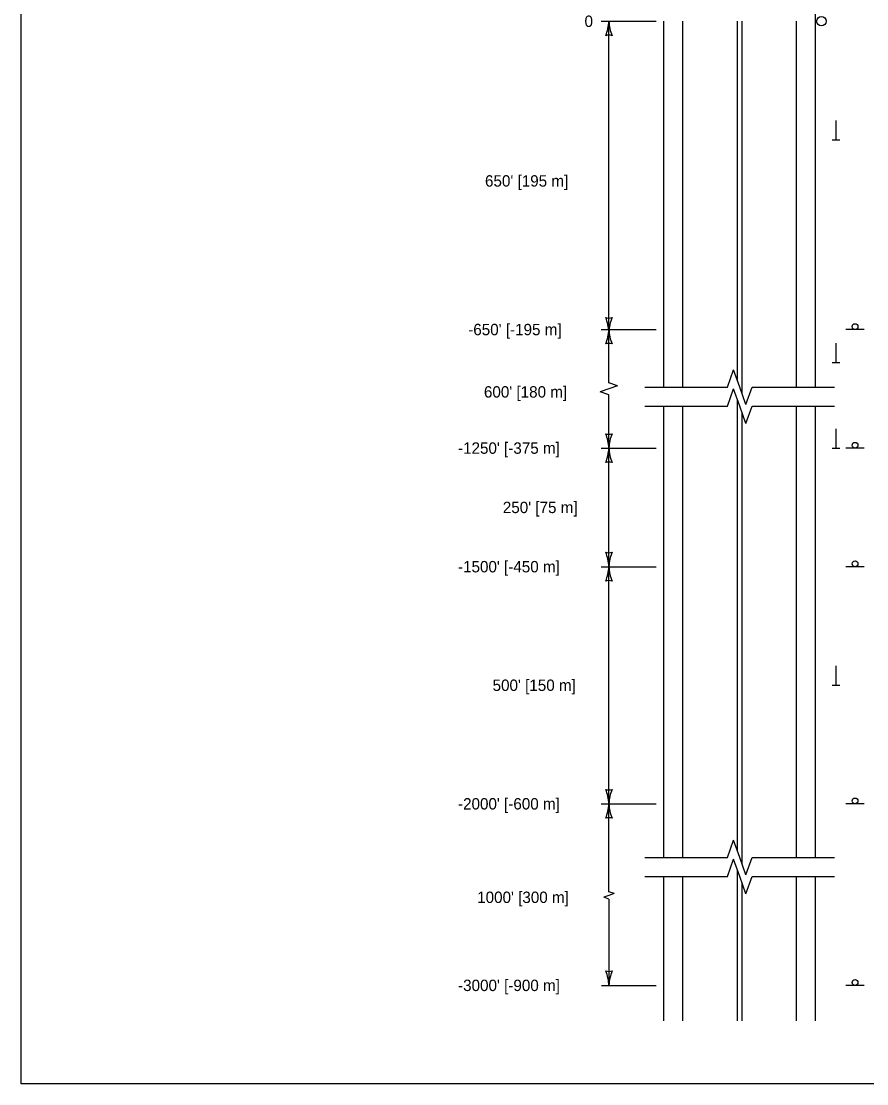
# Model space of a CAD drawing. Extents: x 49991.4 to 50021, y 49987.6 to 50011.4.
# Drawn here: x 49999.38 to 50003.84, y 49987.8 to 49993.4 of the extents above; entities that cross this region are included whole.
import ezdxf

# ---------------------------------------------------------------- set-up
doc = ezdxf.new("R2010")
doc.units = 0
for name, color, linetype in [('Level 1', 7, 'Continuous'), ('Level 2', 7, 'Continuous'), ('Level 3', 7, 'Continuous'), ('Level 6', 7, 'Continuous')]:
    doc.layers.add(name, color=color, linetype=linetype)

msp = doc.modelspace()

# ---------------------------------------------------------------- linework, layer by layer
at = {"layer": 'Level 1'}
for p, q in [((50003.5727, 49991.4704), (50003.5727, 49997.459)), ((50002.7727, 49991.4704), (50002.7727, 49993.3994)), ((50002.8727, 49991.4704), (50002.8727, 49993.3994)), ((50003.1602, 49991.5057), (50003.1602, 49993.3994)), ((50003.1852, 49991.4352), (50003.1852, 49993.3994)), ((50003.4727, 49991.4704), (50003.4727, 49993.3994)), ((50003.6807, 49992.7744), (50003.6807, 49992.8764)), ((50003.6604, 49992.7744), (50003.701, 49992.7744)), ((50003.8287, 49991.7744), (50003.7327, 49991.7744)), ((50003.6807, 49991.5999), (50003.6807, 49991.7018)), ((50003.6604, 49991.5999), (50003.701, 49991.5999)), ((50003.1602, 49989.0262), (50003.1602, 49991.4057)), ((50002.7727, 49988.9909), (50002.7727, 49991.3704)), ((50002.8727, 49988.9909), (50002.8727, 49991.3704)), ((50003.4727, 49988.9909), (50003.4727, 49991.3704)), ((50003.5727, 49988.9909), (50003.5727, 49991.3704)), ((50003.1852, 49988.9556), (50003.1852, 49991.3352)), ((50003.6807, 49991.1494), (50003.6807, 49991.2514)), ((50003.6604, 49991.1494), (50003.701, 49991.1494)), ((50003.8287, 49991.1494), (50003.7327, 49991.1494)), ((50003.8287, 49990.5244), (50003.7327, 49990.5244)), ((50003.6807, 49989.8995), (50003.6807, 49990.0015)), ((50003.6604, 49989.8995), (50003.701, 49989.8995)), ((50003.8287, 49989.2744), (50003.7327, 49989.2744)), ((50002.7727, 49988.1302), (50002.7727, 49988.8909)), ((50002.8727, 49988.1302), (50002.8727, 49988.8909)), ((50003.1602, 49988.1302), (50003.1602, 49988.9262)), ((50003.4727, 49988.1302), (50003.4727, 49988.8909)), ((50003.5727, 49988.1302), (50003.5727, 49988.8909)), ((50003.1852, 49988.1302), (50003.1852, 49988.8556)), ((50003.8287, 49988.3174), (50003.7327, 49988.3174))]:
    msp.add_line(p, q, dxfattribs=at)
msp.add_lwpolyline([(49999.3835, 49998.9992), (50016.7501, 49998.9992), (50016.7501, 49987.7988), (49999.3835, 49987.7988)], close=True, dxfattribs=at)
for centre, radius in [((50003.6032, 49993.3994), 0.025), ((50003.7807, 49991.7896), 0.0152), ((50003.7807, 49991.1646), 0.0152), ((50003.7807, 49990.5396), 0.0152), ((50003.7807, 49989.2896), 0.0152), ((50003.7807, 49988.3326), 0.0152)]:
    msp.add_circle(centre, radius, dxfattribs=at)
at = {"layer": 'Level 3'}
for p, q in [((50002.4427, 49993.3994), (50002.7327, 49993.3994)), ((50002.4827, 49991.7744), (50002.4827, 49993.3994)), ((50002.4427, 49991.7744), (50002.7327, 49991.7744)), ((50002.4827, 49991.4943), (50002.4827, 49991.7744)), ((50002.4827, 49991.4619), (50002.437, 49991.4457)), ((50002.5284, 49991.4781), (50002.4827, 49991.4943)), ((50002.5284, 49991.4781), (50002.4827, 49991.4619)), ((50002.4827, 49991.4295), (50002.437, 49991.4457)), ((50002.4827, 49991.1494), (50002.4827, 49991.4295)), ((50002.4427, 49991.1494), (50002.7327, 49991.1494)), ((50002.4827, 49990.5244), (50002.4827, 49991.1494)), ((50002.4827, 49990.5244), (50002.4827, 49990.7003)), ((50002.4427, 49990.5244), (50002.7327, 49990.5244)), ((50002.4827, 49989.2744), (50002.4827, 49990.5244)), ((50002.4427, 49989.2744), (50002.7327, 49989.2744)), ((50002.4827, 49988.8107), (50002.4827, 49989.2744)), ((50002.4826, 49988.7913), (50002.4552, 49988.7816)), ((50002.4827, 49988.7719), (50002.4552, 49988.7816)), ((50002.51, 49988.801), (50002.4826, 49988.7913)), ((50002.51, 49988.801), (50002.4827, 49988.8107)), ((50002.4827, 49988.7719), (50002.483, 49988.3174)), ((50002.443, 49988.3174), (50002.7327, 49988.3174))]:
    msp.add_line(p, q, dxfattribs=at)
for centre, radius, start, end in [((50002.2606, 49993.4086), 0.2223, 337.456, 357.6395), ((50002.7154, 49993.4109), 0.233, 182.8273, 202.0772), ((50002.4827, 49993.2712), 0.0548, 72.1388, 107.8612), ((50002.4827, 49991.8895), 0.0548, 252.1388, 287.8612), ((50002.25, 49991.7498), 0.233, 2.8273, 22.0772), ((50002.7048, 49991.7521), 0.2223, 157.456, 177.6395), ((50002.2606, 49991.7836), 0.2223, 337.456, 357.6395), ((50002.7154, 49991.7859), 0.233, 182.8273, 202.0772), ((50002.4827, 49991.6462), 0.0548, 72.1388, 107.8612), ((50002.4827, 49991.2776), 0.0548, 252.1388, 287.8612), ((50002.25, 49991.1379), 0.233, 2.8273, 22.0772), ((50002.7048, 49991.1402), 0.2223, 157.456, 177.6395), ((50002.2606, 49991.1586), 0.2223, 337.456, 357.6395), ((50002.7154, 49991.1609), 0.233, 182.8273, 202.0772), ((50002.4827, 49991.0212), 0.0548, 72.1388, 107.8612), ((50002.4827, 49990.6526), 0.0548, 252.1388, 287.8612), ((50002.25, 49990.5129), 0.233, 2.8273, 22.0772), ((50002.7048, 49990.5152), 0.2223, 157.456, 177.6395), ((50002.2606, 49990.5336), 0.2223, 337.456, 357.6395), ((50002.7154, 49990.5359), 0.233, 182.8273, 202.0772), ((50002.4827, 49990.3962), 0.0548, 72.1388, 107.8612), ((50002.4827, 49989.4026), 0.0548, 252.1388, 287.8612), ((50002.25, 49989.2629), 0.233, 2.8273, 22.0772), ((50002.7048, 49989.2652), 0.2223, 157.456, 177.6395), ((50002.2606, 49989.2836), 0.2223, 337.456, 357.6395), ((50002.7154, 49989.2859), 0.233, 182.8273, 202.0772), ((50002.4827, 49989.1462), 0.0548, 72.1388, 107.8612), ((50002.483, 49988.4456), 0.0548, 252.1388, 287.8612), ((50002.2503, 49988.3059), 0.233, 2.8273, 22.0772), ((50002.7051, 49988.3082), 0.2223, 157.456, 177.6395)]:
    msp.add_arc(centre, radius, start, end, dxfattribs=at)
at = {"layer": 'Level 6'}
for p, q in [((50003.1079, 49991.4704), (50003.1403, 49991.5618)), ((50003.1727, 49991.4704), (50003.1403, 49991.5618)), ((50002.6727, 49991.4704), (50003.1079, 49991.4704)), ((50003.1079, 49991.3704), (50003.1403, 49991.4618)), ((50003.1727, 49991.3704), (50003.1403, 49991.4618)), ((50003.2051, 49991.379), (50003.1727, 49991.4704)), ((50003.2051, 49991.379), (50003.2375, 49991.4704)), ((50003.2375, 49991.4704), (50003.6727, 49991.4704)), ((50002.6727, 49991.3704), (50003.1079, 49991.3704)), ((50003.2051, 49991.279), (50003.1727, 49991.3704)), ((50003.2051, 49991.279), (50003.2375, 49991.3704)), ((50003.2375, 49991.3704), (50003.6727, 49991.3704)), ((50003.1079, 49988.9909), (50003.1403, 49989.0823)), ((50003.1727, 49988.9909), (50003.1403, 49989.0823)), ((50002.6727, 49988.9909), (50003.1079, 49988.9909)), ((50003.1079, 49988.8909), (50003.1403, 49988.9823)), ((50003.1727, 49988.8909), (50003.1403, 49988.9823)), ((50003.2051, 49988.8995), (50003.1727, 49988.9909)), ((50003.2051, 49988.8995), (50003.2375, 49988.9909)), ((50003.2375, 49988.9909), (50003.6727, 49988.9909)), ((50002.6727, 49988.8909), (50003.1079, 49988.8909)), ((50003.2051, 49988.7995), (50003.1727, 49988.8909)), ((50003.2051, 49988.7995), (50003.2375, 49988.8909)), ((50003.2375, 49988.8909), (50003.6727, 49988.8909))]:
    msp.add_line(p, q, dxfattribs=at)

# ---------------------------------------------------------------- texts
at = {"layer": 'Level 2'}
for s, p in [('0', (50002.3541, 49993.3694)), ("650' [195 m]", (50001.8293, 49992.5278)), ("-650' [-195 m]", (50001.7408, 49991.7444)), ("600' [180 m]", (50001.8236, 49991.4157)), ("-1250' [-375 m]", (50001.6869, 49991.1194)), ("250' [75 m]", (50001.9232, 49990.8069)), ("-1500' [-450 m]", (50001.6869, 49990.4944)), ("500' [150 m]", (50001.8693, 49989.8694)), ("-2000' [-600 m]", (50001.6869, 49989.2444)), ("1000' [300 m]", (50001.7879, 49988.7516)), ("-3000' [-900 m]", (50001.6872, 49988.2874))]:
    msp.add_text(s, height=0.06, dxfattribs=at).set_placement(p)

doc.saveas('drawing.dxf')
